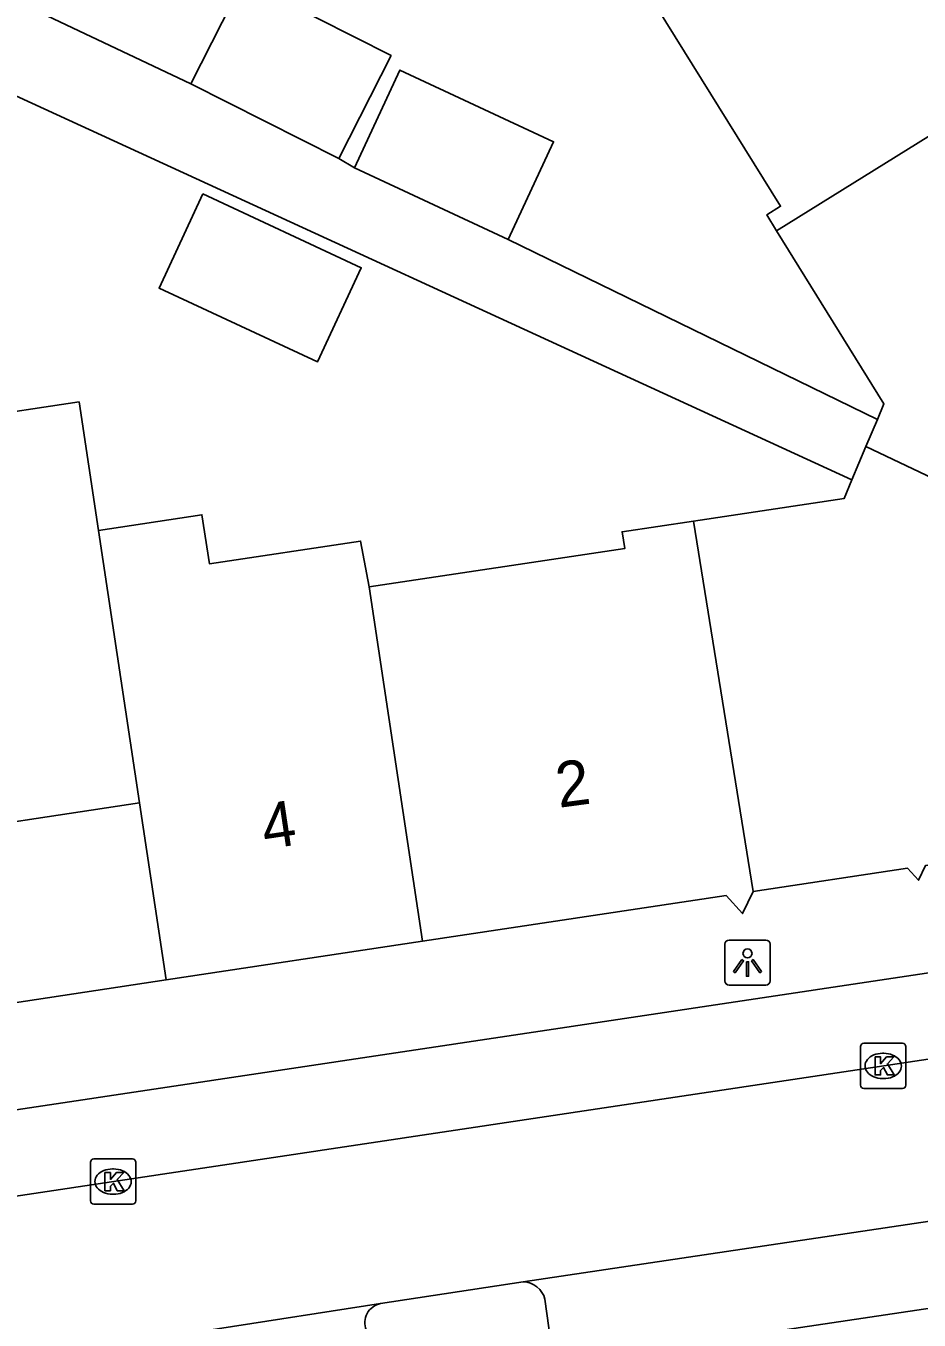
# Model space of a CAD drawing. Extents: x 159280 to 160375, y 384531 to 385872.
# Drawn here: x 160019.62 to 160039.34, y 384945.31 to 384973.88 of the extents above; entities that cross this region are included whole.
import ezdxf

# ---------------------------------------------------------------- set-up
doc = ezdxf.new("R2010")
doc.units = 0
for name, color, linetype in [('IMGEO_Kolk', 7, 'Continuous'), ('IMGEO_Lichtpunt', 7, 'Continuous'), ('IMGEO_Pand', 7, 'Continuous'), ('IMGEO_Pand_nummerreeks', 7, 'Continuous'), ('IMGEO_Parkeervlak_open', 7, 'Continuous'), ('IMGEO_Rijbaan_lokaal_open', 7, 'Continuous'), ('IMGEO_Voetpad_open', 7, 'Continuous')]:
    doc.layers.add(name, color=color, linetype=linetype)

msp = doc.modelspace()

# ---------------------------------------------------------------- linework, layer by layer
at = {"layer": 'IMGEO_Kolk'}
for p, q in [((160038.042, 384950.493), (160038.042, 384951.345)), ((160038.117, 384951.419), (160038.969, 384951.419)), ((160039.043, 384951.345), (160039.043, 384950.493)), ((160038.53, 384951.199), (160038.555, 384951.199)), ((160038.969, 384950.419), (160038.117, 384950.419)), ((160038.553, 384950.639), (160038.528, 384950.639)), ((160021.041, 384947.939), (160021.041, 384948.791)), ((160021.116, 384948.865), (160021.968, 384948.865)), ((160022.042, 384948.791), (160022.042, 384947.939)), ((160021.529, 384948.645), (160021.554, 384948.645)), ((160021.968, 384947.865), (160021.116, 384947.865)), ((160021.552, 384948.085), (160021.527, 384948.085))]:
    msp.add_line(p, q, dxfattribs=at)
for points in [[(160038.042, 384950.493), (160038.042, 384951.345)], [(160038.117, 384951.419), (160038.969, 384951.419)], [(160039.043, 384951.345), (160039.043, 384950.493)], [(160038.363, 384951.119), (160038.486, 384951.119), (160038.486, 384950.968), (160038.616, 384951.119), (160038.78, 384951.119), (160038.634, 384950.968), (160038.787, 384950.719), (160038.635, 384950.719), (160038.55, 384950.883), (160038.486, 384950.816), (160038.486, 384950.719), (160038.363, 384950.719), (160038.363, 384951.119)], [(160038.969, 384950.419), (160038.117, 384950.419)], [(160021.041, 384947.939), (160021.041, 384948.791)], [(160021.116, 384948.865), (160021.968, 384948.865)], [(160022.042, 384948.791), (160022.042, 384947.939)], [(160021.362, 384948.565), (160021.485, 384948.565), (160021.485, 384948.414), (160021.615, 384948.565), (160021.779, 384948.565), (160021.633, 384948.414), (160021.786, 384948.165), (160021.634, 384948.165), (160021.549, 384948.329), (160021.485, 384948.262), (160021.485, 384948.165), (160021.362, 384948.165), (160021.362, 384948.565)], [(160021.968, 384947.865), (160021.116, 384947.865)]]:
    msp.add_lwpolyline(points, dxfattribs=at)
for centre, start, end in [((160038.119, 384951.343), 91.552, 178.448), ((160038.119, 384951.343), 91.552, 178.448), ((160038.967, 384951.343), 1.552, 88.448), ((160038.967, 384951.343), 1.552, 88.448), ((160038.119, 384950.495), 181.552, 268.448), ((160038.119, 384950.495), 181.552, 268.448), ((160038.967, 384950.495), 271.552, 358.448), ((160038.967, 384950.495), 271.552, 358.448), ((160021.118, 384948.789), 91.552, 178.448), ((160021.118, 384948.789), 91.552, 178.448), ((160021.966, 384948.789), 1.552, 88.448), ((160021.966, 384948.789), 1.552, 88.448), ((160021.118, 384947.941), 181.552, 268.448), ((160021.118, 384947.941), 181.552, 268.448), ((160021.966, 384947.941), 271.552, 358.448), ((160021.966, 384947.941), 271.552, 358.448)]:
    msp.add_arc(centre, 0.0765, start, end, dxfattribs=at)
for centre, major_axis, ratio, start_param, end_param in [((160038.529, 384950.919), (-0.387, 0.002), 0.722429, 4.712389, 7.853982), ((160038.554, 384950.919), (-0.39, 0.002), 0.717154, 1.570796, 4.712389), ((160021.528, 384948.365), (-0.387, 0.002), 0.722429, 4.712389, 7.853982), ((160021.553, 384948.365), (-0.39, 0.002), 0.717154, 1.570796, 4.712389)]:
    msp.add_ellipse(centre, major_axis=major_axis, ratio=ratio, start_param=start_param, end_param=end_param, dxfattribs=at)
at = {"layer": 'IMGEO_Lichtpunt'}
for p, q in [((160035.048, 384953.604), (160035.048, 384952.797)), ((160035.048, 384953.604), (160035.048, 384952.797)), ((160035.95, 384953.699), (160035.142, 384953.699)), ((160035.95, 384953.699), (160035.142, 384953.699)), ((160036.044, 384952.797), (160036.044, 384953.604)), ((160036.044, 384952.797), (160036.044, 384953.604)), ((160035.142, 384952.703), (160035.95, 384952.703)), ((160035.142, 384952.703), (160035.95, 384952.703))]:
    msp.add_line(p, q, dxfattribs=at)
for points in [[(160035.422, 384953.268), (160035.461, 384953.24), (160035.273, 384952.978), (160035.235, 384953.005), (160035.422, 384953.268)], [(160035.634, 384953.24), (160035.672, 384953.267), (160035.859, 384953.005), (160035.82, 384952.977), (160035.634, 384953.24)], [(160035.524, 384953.22), (160035.571, 384953.22), (160035.571, 384952.898), (160035.524, 384952.898), (160035.524, 384953.22)]]:
    msp.add_lwpolyline(points, dxfattribs=at)
msp.add_circle((160035.547, 384953.402), 0.0994, dxfattribs=at)
for centre, start, end in [((160035.142, 384953.604), 90, 180), ((160035.142, 384953.604), 90, 180), ((160035.95, 384953.604), 0, 90), ((160035.95, 384953.604), 0, 90), ((160035.142, 384952.797), 180, 270), ((160035.142, 384952.797), 180, 270), ((160035.95, 384952.797), 270, 0), ((160035.95, 384952.797), 270, 360)]:
    msp.add_arc(centre, 0.0946, start, end, dxfattribs=at)
at = {"layer": 'IMGEO_Pand'}
for points in [[(160036.189, 384969.356), (160035.971, 384969.707), (160036.278, 384969.898), (160032.791, 384975.516), (160032.709, 384975.649)], [(160023.26, 384972.606), (160024.412, 384974.881), (160027.678, 384973.228), (160026.527, 384970.953)], [(160043.41, 384973.848), (160036.189, 384969.356)], [(160026.868, 384970.751), (160027.873, 384972.906), (160031.266, 384971.324), (160030.261, 384969.169)], [(160026.527, 384970.953), (160023.26, 384972.606)], [(160030.261, 384969.169), (160026.868, 384970.751)], [(160023.527, 384970.171), (160022.557, 384968.092), (160026.052, 384966.462), (160027.021, 384968.541), (160023.527, 384970.171)], [(160038.413, 384965.194), (160038.558, 384965.539), (160036.189, 384969.356)], [(160021.219, 384962.742), (160020.792, 384965.579), (160018.35, 384965.212), (160017.969, 384967.74), (160015.338, 384967.344), (160015.479, 384965.894)], [(160038.162, 384964.596), (160038.413, 384965.194)], [(160037.852, 384963.858), (160038.162, 384964.596)], [(160044.836, 384961.422), (160038.162, 384964.596)], [(160037.852, 384963.858), (160037.681, 384963.45), (160034.358, 384962.95)], [(160021.219, 384962.742), (160023.504, 384963.087), (160023.667, 384962.005), (160027.006, 384962.508), (160027.197, 384961.494)], [(160022.126, 384956.726), (160021.219, 384962.742)], [(160034.358, 384962.95), (160032.78, 384962.712), (160032.836, 384962.343), (160027.197, 384961.494)], [(160034.358, 384962.95), (160035.669, 384954.769)], [(160027.197, 384961.494), (160028.375, 384953.672)], [(160035.669, 384954.769), (160039.08, 384955.283), (160039.323, 384955.017), (160039.476, 384955.342), (160041.849, 384955.699), (160041.869, 384955.572), (160042.126, 384955.564), (160042.383, 384955.556), (160042.511, 384956.108), (160042.393, 384956.162), (160043.403, 384958.338), (160043.762, 384958.394), (160043.572, 384958.701), (160044.836, 384961.422)], [(160022.126, 384956.726), (160016.975, 384955.951)], [(160022.714, 384952.82), (160022.126, 384956.726)], [(160028.375, 384953.672), (160035.075, 384954.681), (160035.439, 384954.281), (160035.669, 384954.769)], [(160028.375, 384953.672), (160022.714, 384952.82)]]:
    msp.add_lwpolyline(points, dxfattribs=at)
at = {"layer": 'IMGEO_Parkeervlak_open'}
msp.add_lwpolyline([(160031.075, 384945.768), (160031.246, 384944.557)], dxfattribs=at)
msp.add_arc((160030.583, 384945.645), 0.507, 14.0015, 88.5622, dxfattribs=at)
at = {"layer": 'IMGEO_Rijbaan_lokaal_open'}
for points in [[(159993.871, 384944.207), (160041.836, 384951.414)], [(160030.596, 384946.152), (160047.712, 384948.703)], [(160027.445, 384945.671), (160030.596, 384946.152)], [(160020.251, 384944.553), (160027.445, 384945.671)]]:
    msp.add_lwpolyline(points, dxfattribs=at)
at = {"layer": 'IMGEO_Voetpad_open'}
for points in [[(160009.612, 384976.64), (160011.982, 384975.562), (160015.912, 384973.87), (160018.2, 384972.885), (160037.852, 384963.858)], [(160019.679, 384974.298), (160023.26, 384972.606)], [(160026.527, 384970.953), (160026.868, 384970.751)], [(160030.261, 384969.169), (160038.413, 384965.194)], [(159959.209, 384940.91), (160040.921, 384953.179)], [(159960.619, 384943.336), (160000, 384949.373), (160022.714, 384952.82)], [(160047.345, 384948.178), (160047.514, 384946.972), (160047.338, 384946.73), (160031.578, 384944.381)]]:
    msp.add_lwpolyline(points, dxfattribs=at)
msp.add_arc((160027.525, 384945.251), 0.427, 100.7951, 202.0393, dxfattribs=at)

# ---------------------------------------------------------------- texts
at = {"layer": 'IMGEO_Pand_nummerreeks'}
for s, rotation, p in [('2', 7.6261, (160031.383, 384956.617)), ('4', 8.56, (160024.898, 384955.697))]:
    msp.add_text(s, height=1, rotation=rotation, dxfattribs=at).set_placement(p)

doc.saveas('drawing.dxf')
